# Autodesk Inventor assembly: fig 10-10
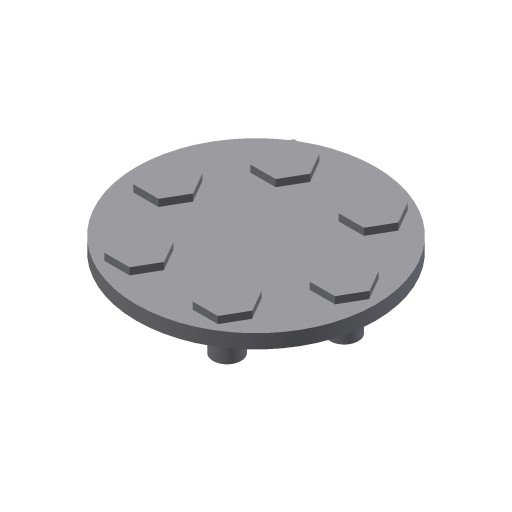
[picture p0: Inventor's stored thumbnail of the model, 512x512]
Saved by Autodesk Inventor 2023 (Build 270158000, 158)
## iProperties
Created: 2008-05
Part Number: fig 10-10
Document SubType Name: Assembly
Designer: CADCIM
Author: CADCIM
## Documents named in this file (3)
- D:\PROJECTS\Project 2022\Autodesk Inventor For Professional 2023\RESOURCES INVENTOR 2023\RESOURCES INVENTOR 2023\Inventor_2023_Part\Inventor_2023_Part\c10_Inv_2023_prt\fig 10-10.iam
- D:\PROJECTS\Project 2022\Autodesk Inventor For Professional 2023\RESOURCES INVENTOR 2023\RESOURCES INVENTOR 2023\Inventor_2023_Part\Inventor_2023_Part\c10_Inv_2023_prt\Part4.ipt
- D:\PROJECTS\Project 2022\Autodesk Inventor For Professional 2023\RESOURCES INVENTOR 2023\RESOURCES INVENTOR 2023\Inventor_2023_Part\Inventor_2023_Part\c10_Inv_2023_prt\Part5.ipt
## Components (7 placed, 2 different names)
1. Part4:1
2. Part5:1
3. Part5:2
4. Part5:3
5. Part5:4
6. Part5:5
7. Part5:6
